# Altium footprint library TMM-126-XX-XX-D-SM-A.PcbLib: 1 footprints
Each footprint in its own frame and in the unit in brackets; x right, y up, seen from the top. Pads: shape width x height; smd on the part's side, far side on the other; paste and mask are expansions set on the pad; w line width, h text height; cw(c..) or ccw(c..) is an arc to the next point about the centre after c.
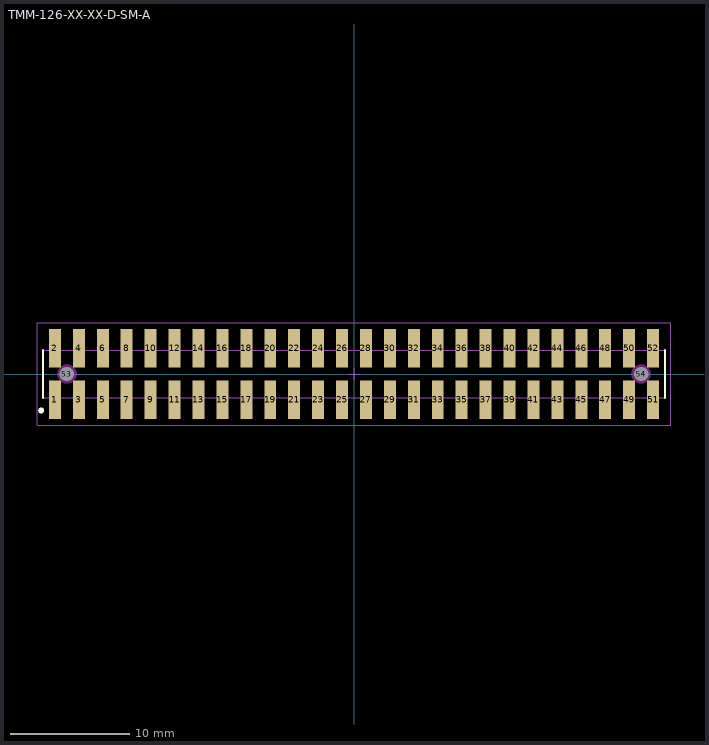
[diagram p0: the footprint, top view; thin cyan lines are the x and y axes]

## TMM-126-XX-XX-D-SM-A [mm] "2.00mm pitch, 52 pin, terminal strip; double row, w/alignment pins, SMT"
height 2.77
pads (54):
  rect 1x3.2 smd mask+0: 1(-25,-2.15) 2(-25,2.15) 3(-23,-2.15) 4(-23,2.15) 5(-21,-2.15) 6(-21,2.15) 7(-19,-2.15) 8(-19,2.15) 9(-17,-2.15) 10(-17,2.15) 11(-15,-2.15) 12(-15,2.15) 13(-13,-2.15) 14(-13,2.15) 15(-11,-2.15) 16(-11,2.15) 17(-9,-2.15) 18(-9,2.15) 19(-7,-2.15) 20(-7,2.15) 21(-5,-2.15) 22(-5,2.15) 23(-3,-2.15) 24(-3,2.15) 25(-1,-2.15) 26(-1,2.15) 27(1,-2.15) 28(1,2.15) 29(3,-2.15) 30(3,2.15) 31(5,-2.15) 32(5,2.15) 33(7,-2.15) 34(7,2.15) 35(9,-2.15) 36(9,2.15) 37(11,-2.15) 38(11,2.15) 39(13,-2.15) 40(13,2.15) 41(15,-2.15) 42(15,2.15) 43(17,-2.15) 44(17,2.15) 45(19,-2.15) 46(19,2.15) 47(21,-2.15) 48(21,2.15) 49(23,-2.15) 50(23,2.15) 51(25,-2.15) 52(25,2.15)
  round 1 hole 1.2 unplated mask+0: 53(-24,0) 54(24,0)
Top Overlay:
  circle w0.25: c-26.15,-3.05 r0.125
  lines w0.2: -26,-2 -26,2 ; 26,-2 26,2
Keep-Out Layer:
  pour cut-out: 24.807,0 24.779,0.209 24.699,0.403 24.571,0.571 24.403,0.699 24.209,0.779 24,0.807 23.791,0.779 23.597,0.699 23.429,0.571 23.301,0.403 23.221,0.209 23.193,0 23.221,-0.209 23.301,-0.403 23.429,-0.571 23.597,-0.699 23.791,-0.779 24,-0.807 24.209,-0.779 24.403,-0.699 24.571,-0.571 24.699,-0.403 24.779,-0.209
  pour cut-out: -23.193,0 -23.221,0.209 -23.301,0.403 -23.429,0.571 -23.597,0.699 -23.791,0.779 -24,0.807 -24.209,0.779 -24.403,0.699 -24.571,0.571 -24.699,0.403 -24.779,0.209 -24.807,0 -24.779,-0.209 -24.699,-0.403 -24.571,-0.571 -24.403,-0.699 -24.209,-0.779 -24,-0.807 -23.791,-0.779 -23.597,-0.699 -23.429,-0.571 -23.301,-0.403 -23.221,-0.209
Mechanical 12:
  lines w0.001: -26,-2 -26,2 26,2 26,-2 -26,-2
Mechanical 13:
  lines w0.1: -26,-2 -26,2 26,2 26,-2 -26,-2
  text ".Designator" at 0,-0.127 h1.52
Mechanical 15:
  lines w0.05: -0.5,0 0.5,0 ; 0,-0.5 0,0.5 ; -26.5,-4.3 -26.5,4.3 26.5,4.3 26.5,-4.3 -26.5,-4.3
